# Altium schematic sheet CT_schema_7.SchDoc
size 251 x 159 mm
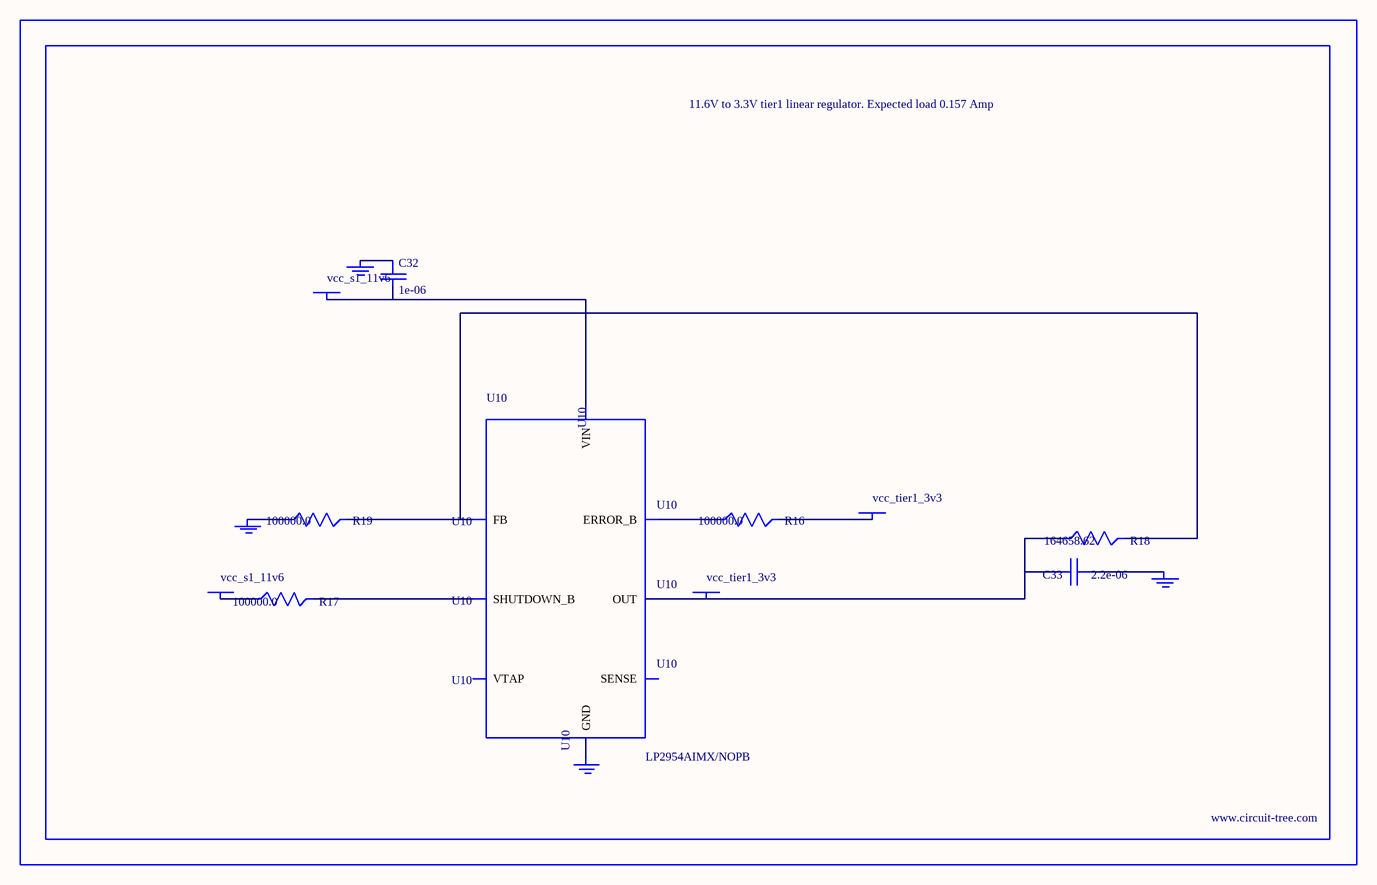
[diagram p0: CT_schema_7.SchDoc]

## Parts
BORDER6  (no value)
C32  1e-06  [EXV-9B]
C33  2.2e-06  [EXV-9B]
GND_INSTANCE_6_0  (no value)
GND_INSTANCE_6_1  (no value)
GND_INSTANCE_6_2  (no value)
GND_INSTANCE_6_3  (no value)
POWER_INSTANCE_6_0  vcc_s1_11v6
POWER_INSTANCE_6_1  vcc_tier1_3v3
POWER_INSTANCE_6_2  vcc_s1_11v6
POWER_INSTANCE_6_3  vcc_tier1_3v3
R16  100000.0  [R0603]
R17  100000.0  [R0603]
R18  164658.62  [R0603]
R19  100000.0  [R0603]
U10  LP2954AIMX/NOPB  [LP2954]

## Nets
NetC32_1: C32.1 GND_INSTANCE_6_2.0(GND)
NetC32_2: C32.2 POWER_INSTANCE_6_2.0(PWR) U10.8(VIN)
NetC33_1: C33.1 GND_INSTANCE_6_0.0(GND)
NetC33_2: C33.2 POWER_INSTANCE_6_3.0(PWR) R18.1 U10.1(OUT)
NetGND_INSTANCE_6_1_0: GND_INSTANCE_6_1.0(GND) R19.1
NetGND_INSTANCE_6_3_0: GND_INSTANCE_6_3.0(GND) U10.4(GND)
NetPOWER_INSTANCE_6_0_0: POWER_INSTANCE_6_0.0(PWR) R17.1
NetPOWER_INSTANCE_6_1_0: POWER_INSTANCE_6_1.0(PWR) R16.2
NetR16_1: R16.1 U10.5(ERROR_B)
NetR17_2: R17.2 U10.3(SHUTDOWN_B)
NetR18_2: R18.2 R19.2 U10.7(FB)

Not connected (* = marked no-connect by the designer): U10 2(SENSE) 6(VTAP)

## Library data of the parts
BORDER6 = BORDER_PAGE6
C32 = EDK105M050A9BAA
C33 = EDK225M050A9BAA
GND_INSTANCE_6_0-GND_INSTANCE_6_3 = GND
POWER_INSTANCE_6_0-POWER_INSTANCE_6_3 = PWR
R16 R17 R19 = RC0603JR-07100KL
R18 = R18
